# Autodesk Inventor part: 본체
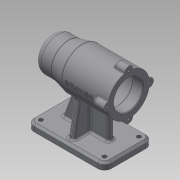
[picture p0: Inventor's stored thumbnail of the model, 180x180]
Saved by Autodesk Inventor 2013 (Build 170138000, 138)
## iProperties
Created: 2019-07
Part Number: 본체
Material: 일반
Document SubType Name: Modeling
Designer: Administrator
Density: 1 g/cm^3
Author: Administrator
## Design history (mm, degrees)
sketch "스케치1"
  geometry: L1 (-56, 0)-(56, 0); L2 (56, 0)-(56, 21); L3 (56, 30)-(-11, 30); L4 (-11, 30)-(-31, 25); L5 (-31, 25)-(-56, 25); L6 (-56, 25)-(-56, 0); L7 (56, 21)-(41, 21); L8 (41, 21)-(41, 24); L9 (41, 24)-(-13, 24); L10 (-13, 24)-(-13, 21); L11 (-13, 21)-(-25, 21); L12 (-25, 21)-(-25, 17.5); L13 (-25, 17.5)-(-43, 17.5); L14 (-43, 17.5)-(-43, 16); L15 (-43, 16)-(-47, 16); L16 (-47, 16)-(-47, 10.5); L17 (-47, 10.5)-(-50, 10.5); L18 (-50, 10.5)-(-50, 0); L19 (56, 21)-(56, 30); 2 further points
  constraints: 38 end point, 9 horizontal, 9 vertical, 2 midpoint, 1 coincident, 1 point on line
  dimensions: "d0" = 112 distance of L1.start L1.end; "d2" = 60 diameter of L3 L1; "d3" = 50 diameter of L5 L1; "d4" = 25 distance from line of L4.end L6; "d5" = 45 distance from line of L3.end L6; "d6" = 42 diameter of L7 L1; "d7" = 48 diameter of L9 L1; "d8" = 42 diameter of L11 L1; "d9" = 35 diameter of L13 L1; "d11" = 32 diameter of L15 L1; "d12" = 21 diameter of L17 L1; "d13" = 3 distance between parallel lines of L16 L18; "d14" = 15 distance between parallel lines of L2 L8; "d15" = 54 distance between parallel lines of L8 L10; "d16" = 12 distance between parallel lines of L12 L10; "d17" = 4 distance between parallel lines of L14 L16; "d18" = 18 distance between parallel lines of L12 L14
revolve "회전1" sketch "스케치1" stored, may be unused: angle "d19" = 90 deg
sketch "스케치2"
  geometry: C1 r 21 at (0, 0) reference; C2 r 6 at (0, 30)
  constraints: 1 centre point, 1 vertical alignment
  dimensions: "d20" = 30 distance of C1.centre C2.centre; "d21" = 12 diameter of C2
extrude "돌출1" join sketch "스케치2" distance "d22" = 16; taper "d23" = 0 deg
hole "구멍1" diameter "d26" = 3.242; stored, may be unused: countersink angle "d30" = 90 deg, drill point angle "d32" = 118 deg; dims "d24" = 10, "d25" = 10, "d27" = 8, "d28" = 4, "d29" = 2, "d31" = 11
fillet "모깎기1" dims "d33" = 3
fillet "모깎기2" dims "d34" = 1
node "작업 평면1"
sketch "스케치3"
  geometry: L1 (56, 35)-(-56, 35); L2 (-56, 35)-(-56, -35); L3 (-56, -35)-(56, -35); L4 (56, -35)-(56, 35); L5 (56, 35)-(-56, -35); L6 (-56, 35)-(56, -35); 1 further point
  constraints: 12 end point, 2 midpoint, 2 parallel, 1 horizontal, 1 perpendicular
  dimensions: "d39" = 112 distance of L2.end L3.end; "d41" = 70 distance of L1.end L2.end
extrude "돌출2" join sketch "스케치3" distance "d42" = 10; taper "d43" = 0 deg
fillet "모깎기3" dims "d44" = 10
sketch "스케치4"
  geometry: A1 r 10 centre (-46, 25) between (-46, 35) and (-56, 25) reference; A2 r 10 centre (-46, -25) between (-56, -25) and (-46, -35) reference; A3 r 10 centre (46, -25) between (46, -35) and (56, -25) reference; A4 r 10 centre (46, 25) between (56, 25) and (46, 35) reference; 5 further points
  constraints: 4 coincident
hole "구멍2" sketch "스케치4" at (-46, 25), (-46, -25), (46, -25), (46, 25) diameter "d45" = 6; stored, may be unused: countersink angle "d49" = 90 deg, drill point angle "d51" = 118 deg; dims "d46" = 8, "d47" = 4, "d48" = 2, "d50" = 11
sketch "스케치5"
  geometry: L1 (-56, 25)-(-56, -25) reference; L2 (56, -25)-(56, 25) reference; L3 (-36, 4)-(31, 4); L4 (31, 4)-(31, -4); L5 (31, -4)-(-36, -4); L6 (-36, -4)-(-36, 4); 2 further points
  constraints: 8 end point, 2 parallel, 1 horizontal, 1 horizontal alignment, 1 midpoint, 1 perpendicular
  dimensions: "d52" = 25 distance between parallel lines of L2 L4; "d53" = 20 distance between parallel lines of L1 L6; "d54" = 8 distance between parallel lines of L5 L3
extrude "돌출3" join sketch "스케치5" stored distance "d55" = 10; taper "d56" = 0 deg
feature "면 기울기1" dims angle "d57" = 20 deg
chamfer "모따기1" distance "d58" = 3; stored, may be unused: second distance "d59" = 2, angle "d60" = 45 deg
sketch "스케치6"
  geometry: L1 (-80, 35)-(-73, 35) reference; L2 (-70, 32)-(-70, 25) reference; L3 (-70, 25)-(-70, -25) reference; L4 (-70, 28)-(-52.307, 24.88); 1 further point
  constraints: 2 end point, 1 point on line
  dimensions: "d61" = 7 distance from line of L4.start L1; "d62" = 100 deg angle of L2 L4
feature "리브1" sketch "스케치6" dims "d63" = 1, "d64" = 8, "d65" = 0, "d66" = 0, "d67" = 1, "d68" = 1
node "작업 평면2"
sketch "스케치7"
  geometry: L1 (33.5, 36)-(33.5, 30.171) reference; 2 further points
  constraints: 1 horizontal alignment, 1 other
  dimensions: "d69" = 42 distance from line of L1 point (-8.5, 0)
feature "엠보싱1" sketch "스케치7" dims "d70" = 0.5, "d71" = 0
fillet "모깎기4" dims "d72" = 0.3
fillet "모깎기5" dims "d73" = 3
chamfer "모따기2" distance "d74" = 1; stored, may be unused: second distance "d75" = 2, angle "d76" = 45 deg
fillet "모깎기6" dims "d77" = 10
fillet "모깎기7" dims "d78" = 3
fillet "모깎기8" dims "d79" = 3
fillet "모깎기9" dims "d80" = 3
node "솔리드1"
pattern_circular "원형 패턴1" dims "d36" = 360 deg
mirror "대칭1"
